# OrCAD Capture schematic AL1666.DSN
size Custom; title: AL1666 -HIGH PERFORMANCE DIMMABLE LED CONTROLLER; rev: 1.0; note: DS42417 Rev. 1 - 2
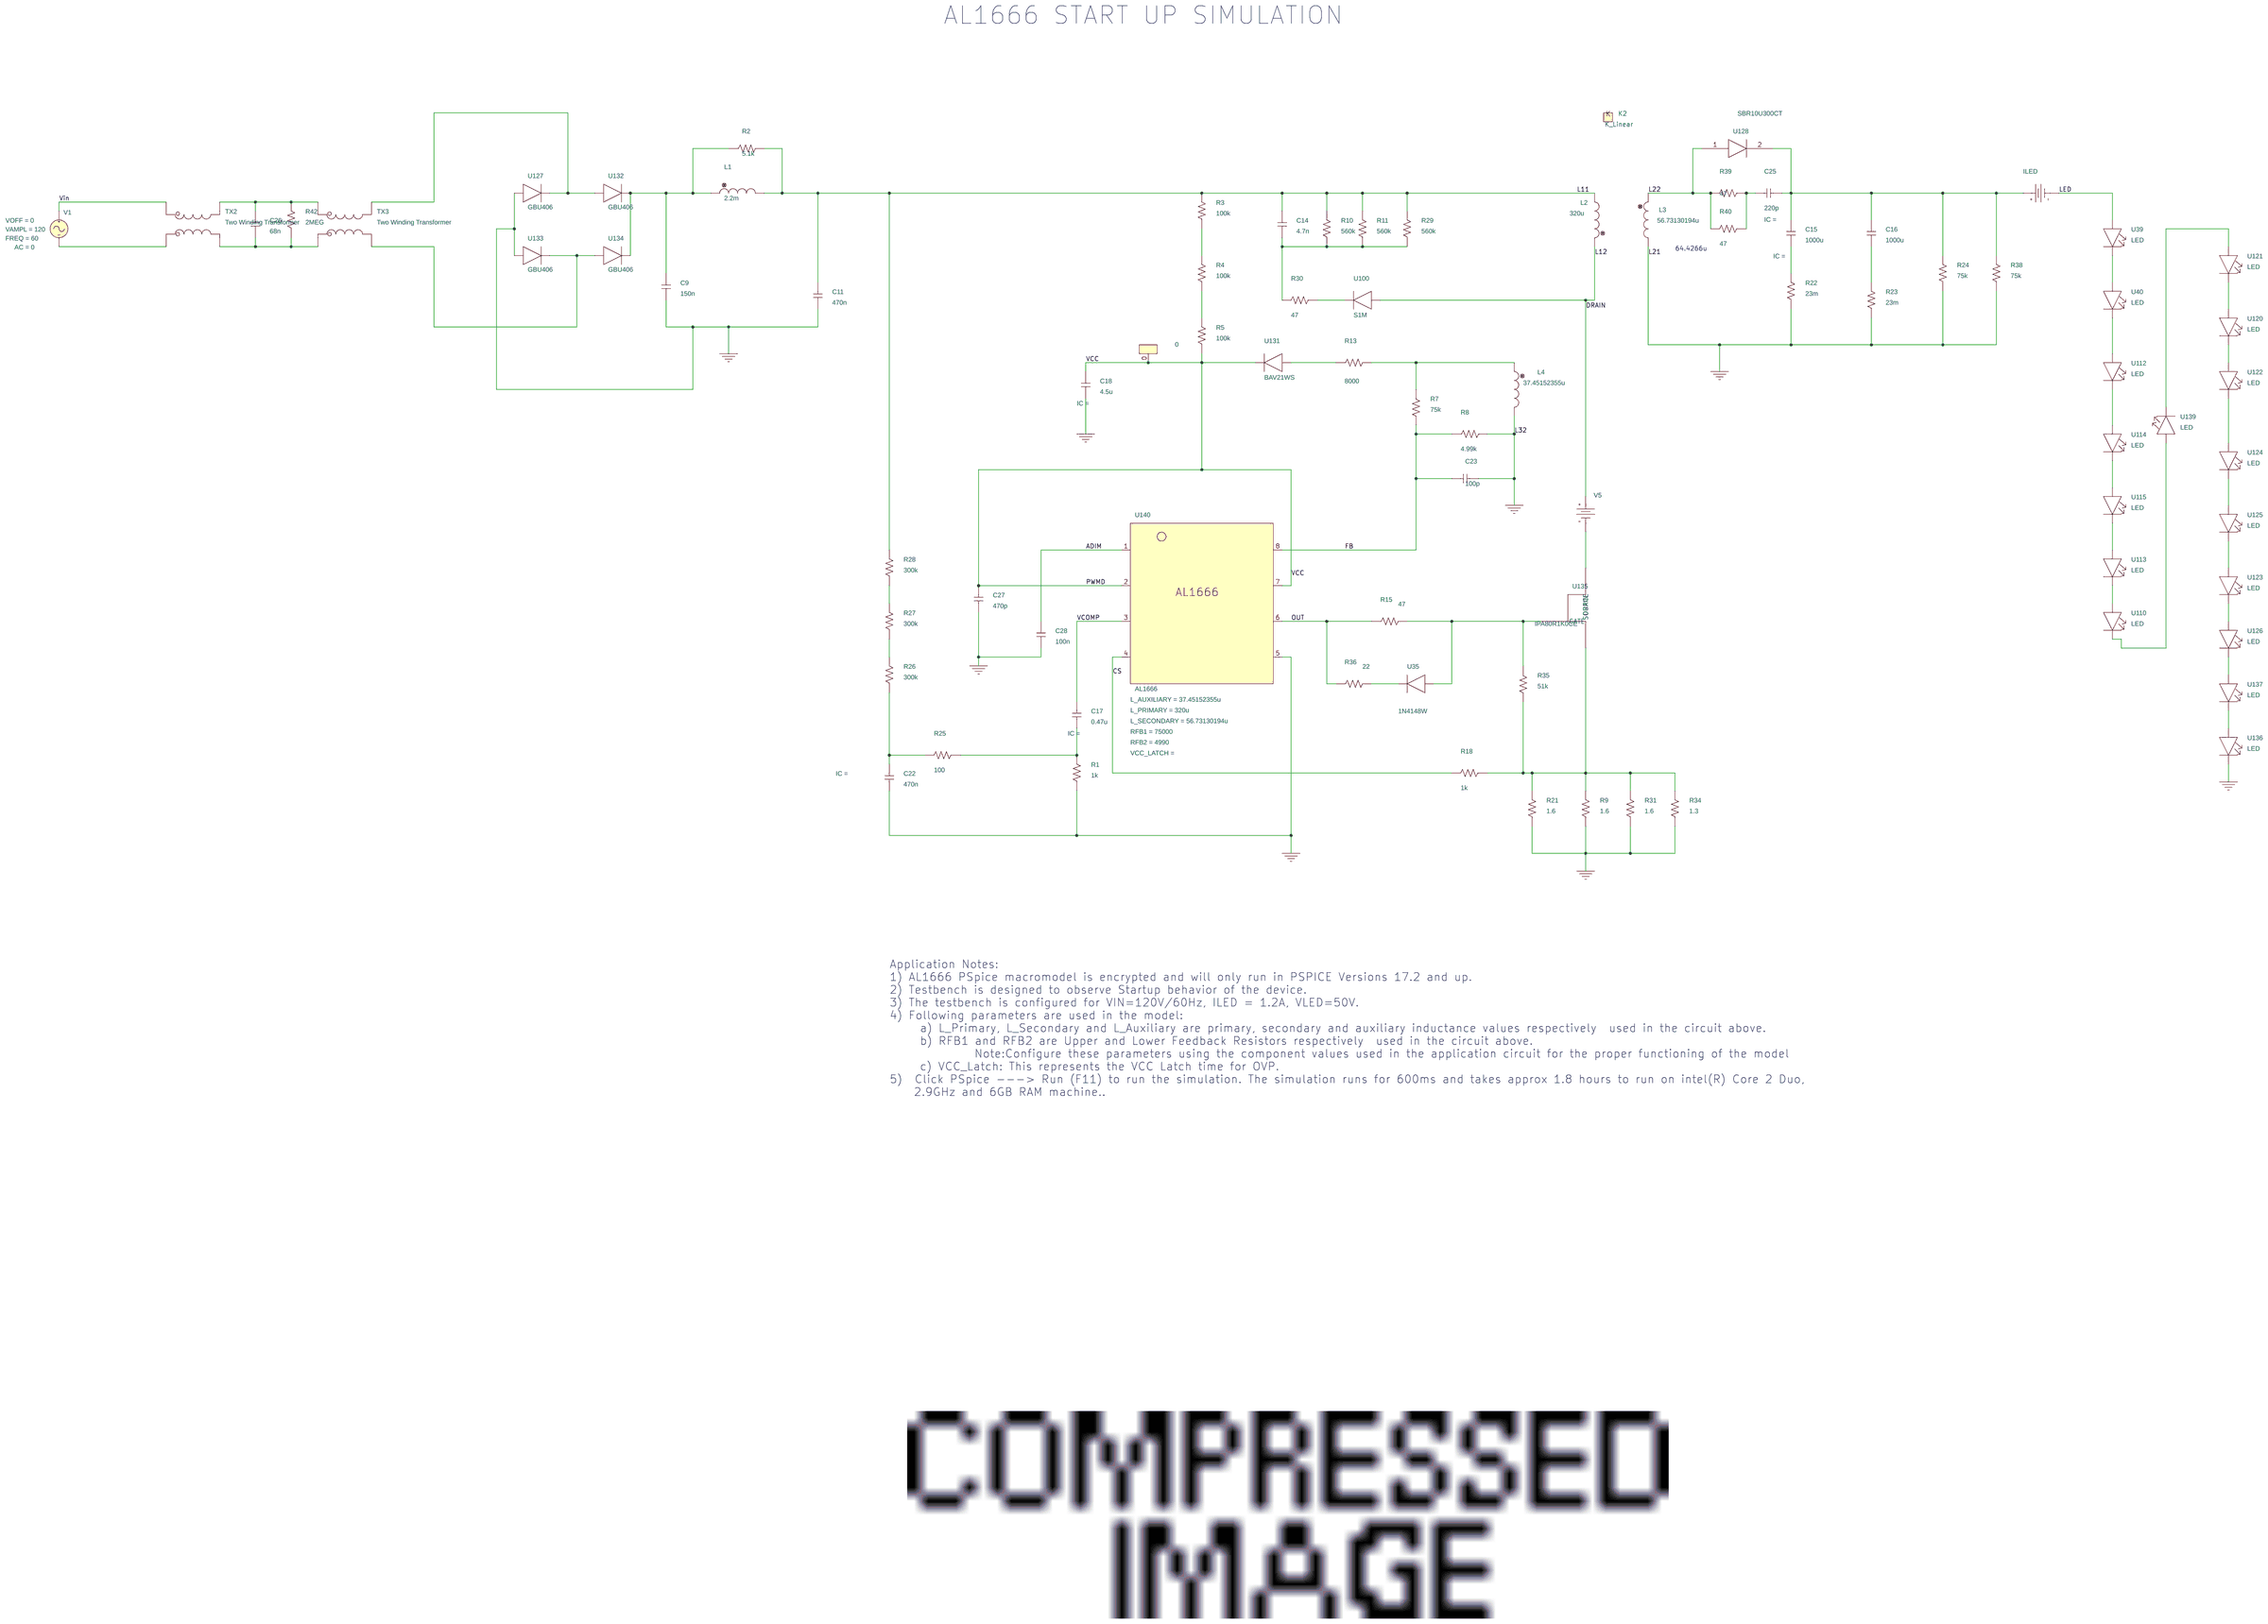
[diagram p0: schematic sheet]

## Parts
C9  150n  [RAD/CK05]
C11  470n  [RAD/CK05]
C14  4.7n  [RAD/CK05]
C15  1000u  [RAD/CK05]
C16  1000u  [RAD/CK05]
C17  0.47u  [RAD/CK05]
C18  4.5u  [RAD/CK05]
C22  470n  [RAD/CK05]
C23  100p  [RAD/CK05]
C25  220p  [RAD/CK05]
C26  68n  [RAD/CK05]
C27  470p  [RAD/CK05]
C28  100n  [RAD/CK05]
IC3  0
ILED  VDC
K2  K_Linear
L1  2.2m  [DISC/.350x.175/LS.200x.100/.034]
L2  320u  [DISC/.350x.175/LS.200x.100/.034]
L3  56.73130194u  [DISC/.350x.175/LS.200x.100/.034]
L4  37.45152355u  [DISC/.350x.175/LS.200x.100/.034]
R1  1k  [AX/RC05]
R2  5.1k  [AX/RC05]
R3  100k  [AX/RC05]
R4  100k  [AX/RC05]
R5  100k  [AX/RC05]
R7  75k  [AX/RC05]
R8  4.99k  [AX/RC05]
R9  1.6  [AX/RC05]
R10  560k  [AX/RC05]
R11  560k  [AX/RC05]
R13  8000  [AX/RC05]
R15  47  [AX/RC05]
R18  1k  [AX/RC05]
R21  1.6  [AX/RC05]
R22  23m  [AX/RC05]
R23  23m  [AX/RC05]
R24  75k  [AX/RC05]
R25  100  [AX/RC05]
R26  300k  [AX/RC05]
R27  300k  [AX/RC05]
R28  300k  [AX/RC05]
R29  560k  [AX/RC05]
R30  47  [AX/RC05]
R31  1.6  [AX/RC05]
R34  1.3  [AX/RC05]
R35  51k  [AX/RC05]
R36  22  [AX/RC05]
R38  75k  [AX/RC05]
R39  47  [AX/RC05]
R40  47  [AX/RC05]
R42  2MEG  [AX/RC05]
TX2  Two Winding Transformer
TX3  Two Winding Transformer
U35  1N4148W
U39  LED
U40  LED
U100  S1M
U110  LED
U112  LED
U113  LED
U114  LED
U115  LED
U120  LED
U121  LED
U122  LED
U123  LED
U124  LED
U125  LED
U126  LED
U127  GBU406
U128  SBR10U300CT
U131  BAV21WS
U132  GBU406
U133  GBU406
U134  GBU406
U135  IPA80R1K0CE
U136  LED
U137  LED
U139  LED
U140  AL1666
V1  VSIN
V5  VDC

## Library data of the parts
C9 C11 C14-C18 C22 C23 C25-C28 = C
IC3 = IC1
ILED V5 = VDC
K2 = K_Linear: COUPLING: 0.9999; L1: L2; L2: L3; L3: L4
L1-L4 = L
R1-R5 R7-R11 R13 R15 R18 R21-R31 R34-R36 R38-R40 R42 = R
TX2 = ST: AppProp: ST_Model,1m,10m,10m,1,100n
TX3 = ST: AppProp: ST_Model,30m,10m,10m,1,100n
U35 = 1N4148W
U39 U40 U110 U112-U115 U120-U126 U136 U137 U139 = LED
U100 = S1M
U127 U132-U134 = GBU406
U128 = SBR10U300CT
U131 = BAV21WS
U135 = IPA80R1K0CE
U140 = AL1666: L_AUXILIARY: 37.45152355u; L_PRIMARY: 320u; L_SECONDARY: 56.73130194u; RFB1: 75000; RFB2: 4990
V1 = VSIN: AC: 0; AppProp: Sine$Voltage$0$-1; DC: 0; FREQ: 60; VAMPL: 120; VOFF: 0

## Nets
Vin: TX2.3 V1.1(+)
0: C9.1 C11.1 C18.2 C22.2 C23.2 C27.1 C28.1 L3.2 L4.2 R1.1 R8.2 R9.1 R21.1 R22.1 R23.1 R24.1 R31.1 R34.1 R38.1 U127.1 U133.1 U136.2 U140.5(GND)
ADIM: C28.2 U140.1(ADIM)
CS: R18.2 U140.4(CS)
DRAIN: L2.1 U100.1 V5.0(+)
FB: C23.1 R7.2 R8.1 U140.8(FB)
L11: C11.2 C14.2 L1.2 L2.2 R2.2 R3.2 R10.2 R11.2 R28.2 R29.2
L22: L3.1 R39.2 R40.2 U128.1
LED: ILED.1(-) U39.1
OUT: R15.1 R36.1 U140.6(OUT)
PWMD: C18.1 C27.2 IC3.0(+) R5.1 U131.2 U140.2(PWMD) U140.7(VCC)
VCOMP: C17.1 U140.3(COMP)
N498604: TX3.4 U127.2 U132.1
N498684: C9.2 L1.1 R2.1 U132.2 U134.2
N498710: C15.1 C16.1 C25.2 ILED.0(+) R24.2 R38.2 U128.2
N498960: C25.1 R39.1 R40.1
N499036: C26.2 R42.2 TX2.4 TX3.3
N499374: R3.1 R4.2
N499436: U121.1 U139.2
N499452: C26.1 R42.1 TX2.2 TX3.1
N499460: C14.1 R10.1 R11.1 R29.1 R30.2
N499464: TX2.1 V1.2(-)
N499486: TX3.2 U133.2 U134.1
N499572: C15.2 R22.2
N499578: C16.2 R23.2
N499596: U39.2 U40.1
N499728: U120.1 U121.2
N499750: R4.1 R5.2
N499856: R30.1 U100.2
N499892: U40.2 U112.1
N500010: U120.2 U122.1
N500098: R13.1 U131.1
N500104: L4.1 R7.1 R13.2
N500216: U112.2 U114.1
N500250: U122.2 U124.1
N500360: U110.2 U139.1
N500388: U114.2 U115.1
N500440: U124.2 U125.1
N500528: U113.1 U115.2
N500542: U135.1(DRAIN) V5.1(-)
N500548: U123.1 U125.2
N500638: R27.2 R28.1
N500660: U110.1 U113.2
N500698: U123.2 U126.1
N500798: R15.2 R35.1 U35.1 U135.2(GATE)
N500858: R26.2 R27.1
N500942: R9.2 R18.1 R21.2 R31.2 R34.2 R35.2 U135.3(SOURCE)
N500964: R36.2 U35.2
N500974: U126.2 U137.1
N501120: C22.1 R25.2 R26.1
N501238: U136.1 U137.2
N501244: C17.2 R1.2 R25.1

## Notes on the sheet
- AL1666 START UP SIMULATION
- 64.4266u
- Application Notes:
  1) AL1666 PSpice macromodel is encrypted and will only run in PSPICE Versions 17.2 and up.
  2) Testbench is designed to observe Startup behavior of the device.
  3) The testbench is configured for VIN=120V/60Hz, ILED = 1.2A, VLED=50V.
  4) Following parameters are used in the model:
       a) L_Primary, L_Secondary and L_Auxiliary are primary, secondary and auxiliary inductance values respectively  used in the circuit above.
       b) RFB1 and RFB2 are Upper and Lower Feedback Resistors respectively  used in the circuit above.
                Note:Configure these parameters using the component values used in the application circuit for the proper functioning of the model
       c) VCC_Latch: This represents the VCC Latch time for OVP.
  5)  Click PSpice ---> Run (F11) to run the simulation. The simulation runs for 600ms and takes approx 1.8 hours to run on intel(R) Core 2 Duo,
      2.9GHz and 6GB RAM machine..
